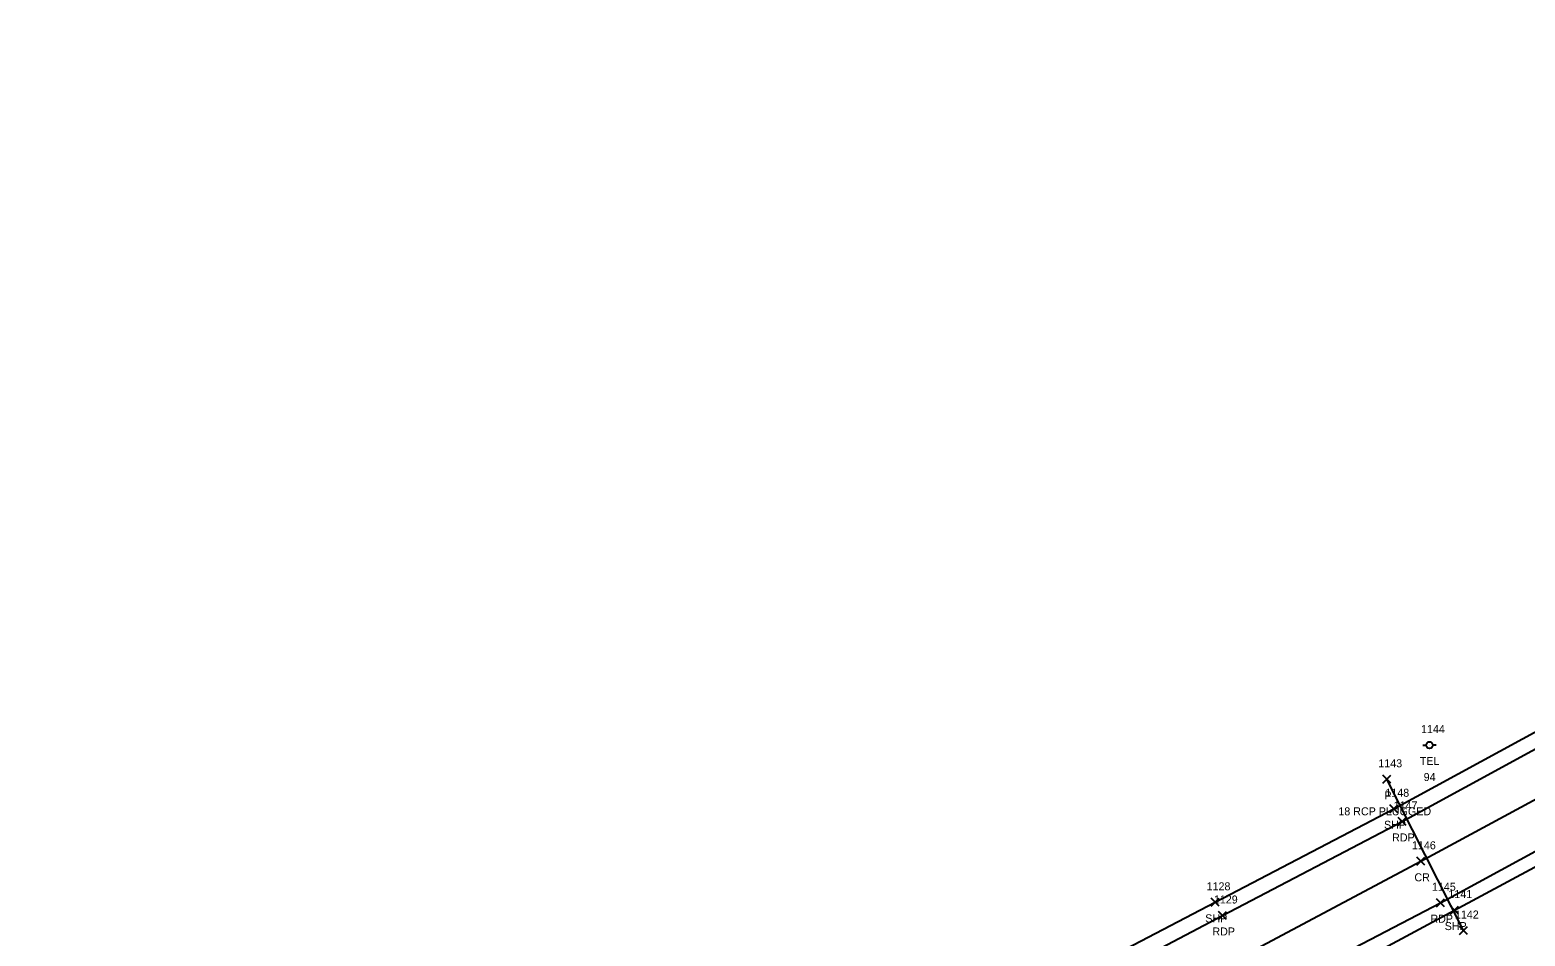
# Model space of a CAD drawing. Extents: x 1606530 to 1613020, y 784959 to 789666.
# Drawn here: x 1608211.4 to 1608585, y 788110.1 to 788336.6 of the extents above; entities that cross this region are included whole.
import ezdxf

# ---------------------------------------------------------------- set-up
doc = ezdxf.new("R2010")
doc.units = 0
for name, color, linetype in [('D_A', 7, 'Continuous'), ('D_C', 7, 'Continuous'), ('D_I', 7, 'Continuous'), ('D_TIC', 7, 'Continuous'), ('DCP', 7, 'Continuous'), ('P_A', 7, 'Continuous'), ('P_I', 7, 'Continuous'), ('P_TIC', 7, 'Continuous'), ('PET', 7, 'Continuous'), ('PRC', 7, 'Continuous'), ('PSP', 7, 'Continuous'), ('U_A', 7, 'Continuous'), ('U_C', 7, 'Continuous'), ('U_I', 7, 'Continuous'), ('UP', 7, 'Continuous')]:
    doc.layers.add(name, color=color, linetype=linetype)

msp = doc.modelspace()

# ---------------------------------------------------------------- linework, layer by layer
at = {"layer": 'D_TIC'}
for points in [[(1608549.46, 788148.28), (1608551.46, 788150.28)], [(1608551.46, 788148.28), (1608549.46, 788150.28)], [(1608568.6, 788110.49), (1608570.6, 788112.49)], [(1608570.6, 788110.49), (1608568.6, 788112.49)]]:
    msp.add_lwpolyline(points, dxfattribs=at)
at = {"layer": 'DCP'}
msp.add_lwpolyline([(1608569.6, 788111.49), (1608550.46, 788149.28)], dxfattribs=at)
at = {"layer": 'P_TIC'}
for points in [[(1608551.21, 788140.92), (1608553.21, 788142.92)], [(1608553.21, 788140.92), (1608551.21, 788142.92)], [(1608553.28, 788137.75), (1608555.28, 788139.75)], [(1608555.28, 788137.75), (1608553.28, 788139.75)], [(1608557.92, 788127.79), (1608559.92, 788129.79)], [(1608559.92, 788127.79), (1608557.92, 788129.79)], [(1608506.55, 788117.54), (1608508.55, 788119.54)], [(1608508.55, 788117.54), (1608506.55, 788119.54)], [(1608562.86, 788117.44), (1608564.86, 788119.44)], [(1608564.86, 788117.44), (1608562.86, 788119.44)], [(1608508.37, 788114.25), (1608510.37, 788116.25)], [(1608510.37, 788114.25), (1608508.37, 788116.25)], [(1608566.38, 788115.6), (1608568.38, 788117.6)], [(1608568.38, 788115.6), (1608566.38, 788117.6)]]:
    msp.add_lwpolyline(points, dxfattribs=at)
at = {"layer": 'PET'}
for points in [[(1608213.49, 787970.47), (1608262.25, 787993.4), (1608276.88, 787999.74), (1608323.57, 788022.14), (1608370.66, 788045.01), (1608417.98, 788068.46), (1608464.64, 788091.66), (1608509.37, 788115.25), (1608554.28, 788138.75), (1608602.43, 788165), (1608652.45, 788192.19), (1608697.7, 788217.31), (1608740.32, 788241.6), (1608780.44, 788265.54), (1608814.8, 788285.27), (1608858.1, 788310.73), (1608896.56, 788332.46)], [(1608222.94, 787950.09), (1608271.33, 787972.62), (1608285.55, 787979.14), (1608332.21, 788001.49), (1608379.48, 788024.01), (1608428.02, 788048.6), (1608475.06, 788071.87), (1608519, 788095), (1608563.86, 788118.44), (1608613.21, 788145.21), (1608663.01, 788172.64), (1608706.97, 788197.28), (1608750.94, 788222.17), (1608791.64, 788245.74), (1608827.2, 788266.24), (1608867.86, 788290.54)]]:
    msp.add_lwpolyline(points, dxfattribs=at)
at = {"layer": 'PRC'}
msp.add_lwpolyline([(1608218.84, 787960.71), (1608267.22, 787983.04), (1608281.29, 787989.52), (1608328.06, 788011.76), (1608375.14, 788034.19), (1608423.06, 788058.55), (1608469.95, 788081.45), (1608514.06, 788104.91), (1608558.92, 788128.79), (1608607.88, 788155.22), (1608657.8, 788182.27), (1608701.47, 788207.47), (1608744.76, 788231.88), (1608785.13, 788255.45), (1608820.6, 788275.76), (1608863.25, 788300.9), (1608901.81, 788322.6)], dxfattribs=at)
at = {"layer": 'PSP'}
for points in [[(1608211.38, 787974.27), (1608260.55, 787996.78), (1608275.47, 788003.59), (1608321.31, 788025.42), (1608369.02, 788048.35), (1608416.07, 788071.69), (1608462.93, 788095.28), (1608507.55, 788118.54), (1608552.21, 788141.92), (1608600.4, 788168.18), (1608650.82, 788195.72), (1608695.96, 788221.19), (1608744.94, 788249.39), (1608760.2, 788258.36), (1608792.98, 788277.31), (1608812.41, 788289.29), (1608855.39, 788314.11), (1608894.81, 788336.59)], [(1608222.38, 787945.84), (1608249.08, 787958.77), (1608292.52, 787977.73), (1608320.86, 787991.5), (1608334.01, 787997.98), (1608381.01, 788020.88), (1608430, 788045.59), (1608476.4, 788068.65), (1608521.08, 788091.65), (1608567.38, 788116.6), (1608615.07, 788142.28), (1608664.87, 788169.33), (1608708.99, 788194), (1608752.22, 788219.24), (1608792.93, 788243.28), (1608830.36, 788265), (1608869.22, 788287.4)]]:
    msp.add_lwpolyline(points, dxfattribs=at)
at = {"layer": 'UP'}
for p, q in [((1608559.47, 788157.84), (1608560.29, 788157.84)), ((1608561.13, 788157.85), (1608561.13, 788157.85)), ((1608562.79, 788157.85), (1608561.96, 788157.85)), ((1608561.96, 788157.85), (1608561.96, 788157.85)), ((1608562.79, 788157.85), (1608562.79, 788157.85))]:
    msp.add_line(p, q, dxfattribs=at)
msp.add_circle((1608561.13, 788157.85), 0.833, dxfattribs=at)

# ---------------------------------------------------------------- texts
at = {"layer": 'D_A'}
msp.add_text('P', height=2, dxfattribs=at).set_placement((1608549.83, 788144.28))
at = {"layer": 'D_C'}
msp.add_text('18 RCP PLUGGED', height=2, dxfattribs=at).set_placement((1608538.34, 788140.28))
at = {"layer": 'D_I'}
for s, p in [('1143', (1608548.33, 788152.28)), ('1142', (1608567.47, 788114.49))]:
    msp.add_text(s, height=2, dxfattribs=at).set_placement(p)
at = {"layer": 'P_A'}
for s, p in [('SHP', (1608549.75, 788136.92)), ('RDP', (1608551.77, 788133.75)), ('CR', (1608557.35, 788123.79)), ('SHP', (1608505.08, 788113.54)), ('RDP', (1608561.34, 788113.44)), ('RDP', (1608506.86, 788110.25)), ('SHP', (1608564.92, 788111.6))]:
    msp.add_text(s, height=2, dxfattribs=at).set_placement(p)
at = {"layer": 'P_I'}
for s, p in [('1148', (1608550.09, 788144.92)), ('1147', (1608552.15, 788141.75)), ('1146', (1608556.74, 788131.79)), ('1128', (1608505.42, 788121.54)), ('1145', (1608561.73, 788121.44)), ('1129', (1608507.24, 788118.25)), ('1141', (1608565.83, 788119.6))]:
    msp.add_text(s, height=2, dxfattribs=at).set_placement(p)
at = {"layer": 'U_A'}
msp.add_text('TEL', height=2, dxfattribs=at).set_placement((1608558.69, 788152.85))
at = {"layer": 'U_C'}
msp.add_text('94', height=2, dxfattribs=at).set_placement((1608559.66, 788148.85))
at = {"layer": 'U_I'}
msp.add_text('1144', height=2, dxfattribs=at).set_placement((1608559, 788160.85))

doc.saveas('drawing.dxf')
